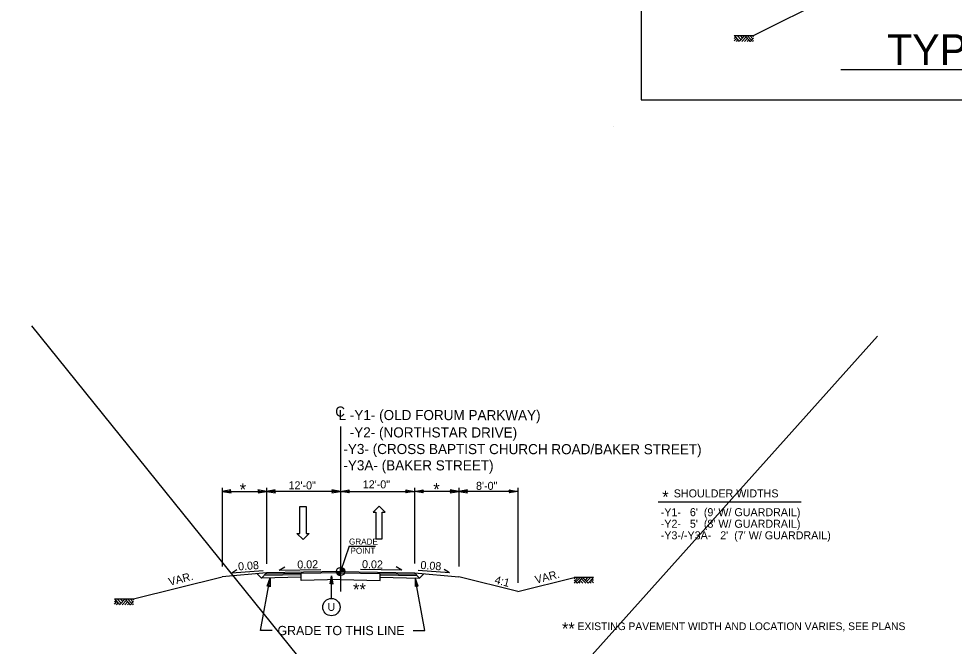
# Model space of a CAD drawing. Extents: x 1904401 to 1905163, y 193929 to 194736.
# Drawn here: x 1904401.4 to 1904553.3, y 194143.4 to 194245.4 of the extents above; entities that cross this region are included whole.
import ezdxf

# ---------------------------------------------------------------- set-up
doc = ezdxf.new("R2010")
doc.units = 0
for name, color, linetype in [('Old_Level_1', 7, 'Continuous'), ('Old_Level_11', 7, 'Continuous'), ('Old_Level_2', 7, 'Continuous'), ('Old_Level_20', 7, 'Continuous'), ('Old_Level_3', 7, 'Continuous'), ('Prop Dimension Text', 7, 'Continuous'), ('Prop Lane Arrow CELL', 7, 'Continuous'), ('Scratch_Level_3', 7, 'Continuous'), ('Typical Arrow Superelevation CELL', 7, 'Continuous'), ('Typical Berm CELL', 7, 'Continuous'), ('Typical Hinge Slope Arterial CELL', 7, 'Continuous'), ('Typical Hinge Slope Interstate CELL', 7, 'Continuous'), ('Typical Terminator CELL', 7, 'Continuous'), ('Typical Text Centerline CELL', 7, 'Continuous')]:
    doc.layers.add(name, color=color, linetype=linetype)

msp = doc.modelspace()

# ---------------------------------------------------------------- linework, layer by layer
at = {"layer": 'Old_Level_1'}
for p, q in [((1904453.68, 194155.54), (1904453.68, 194156.22)), ((1904453.01, 194155.54), (1904453.68, 194155.54)), ((1904454.36, 194155.54), (1904453.68, 194155.54)), ((1904453.68, 194154.87), (1904453.68, 194155.54)), ((1904453.68, 194155.54), (1904453.68, 194154.87))]:
    msp.add_line(p, q, dxfattribs=at)
for points in [[(1904453.69, 194156.22), (1904453.69, 194156.22), (1904453.69, 194155.54)], [(1904453.7, 194156.22), (1904453.7, 194155.54)], [(1904453.72, 194156.22), (1904453.72, 194155.54)], [(1904453.73, 194156.22), (1904453.73, 194155.54)], [(1904453.74, 194156.21), (1904453.74, 194155.54)], [(1904453.76, 194156.21), (1904453.76, 194155.54)], [(1904453.77, 194156.21), (1904453.77, 194155.54)], [(1904453.78, 194156.21), (1904453.78, 194155.54)], [(1904453.8, 194156.21), (1904453.8, 194155.54)], [(1904453.81, 194156.21), (1904453.81, 194155.54)], [(1904453.82, 194156.2), (1904453.82, 194155.54)], [(1904453.84, 194156.2), (1904453.84, 194155.54)], [(1904453.85, 194156.2), (1904453.85, 194155.54)], [(1904453.86, 194156.19), (1904453.86, 194155.54)], [(1904453.88, 194156.19), (1904453.88, 194155.54)], [(1904453.89, 194156.18), (1904453.89, 194155.54)], [(1904453.91, 194156.18), (1904453.91, 194155.54)], [(1904453.92, 194156.18), (1904453.92, 194155.54)], [(1904453.93, 194156.17), (1904453.93, 194155.54)], [(1904453.95, 194156.16), (1904453.95, 194155.54)], [(1904453.96, 194156.16), (1904453.96, 194155.54)], [(1904453.97, 194156.15), (1904453.97, 194155.54)], [(1904453.99, 194156.15), (1904453.99, 194155.54)], [(1904454, 194156.14), (1904454, 194155.54)], [(1904454.01, 194156.13), (1904454.01, 194155.54)], [(1904454.03, 194156.12), (1904454.03, 194155.54)], [(1904454.04, 194156.12), (1904454.04, 194155.54)], [(1904454.05, 194156.11), (1904454.05, 194155.54)], [(1904454.07, 194156.1), (1904454.07, 194155.54)], [(1904454.08, 194156.09), (1904454.08, 194155.54)], [(1904454.09, 194156.08), (1904454.09, 194155.54)], [(1904454.11, 194156.07), (1904454.11, 194155.54)], [(1904454.12, 194156.06), (1904454.12, 194155.54)], [(1904454.13, 194156.04), (1904454.13, 194155.54)], [(1904454.15, 194156.03), (1904454.15, 194155.54)], [(1904454.16, 194156.02), (1904454.16, 194155.54)], [(1904454.18, 194156), (1904454.18, 194155.54)], [(1904454.19, 194155.99), (1904454.19, 194155.54)], [(1904454.2, 194155.97), (1904454.2, 194155.54)], [(1904454.22, 194155.96), (1904454.22, 194155.54)], [(1904454.23, 194155.94), (1904454.23, 194155.54)], [(1904453.01, 194155.54), (1904453.01, 194155.47)], [(1904453.02, 194155.54), (1904453.02, 194155.39)], [(1904453.04, 194155.54), (1904453.04, 194155.34)], [(1904453.05, 194155.54), (1904453.05, 194155.3)], [(1904453.07, 194155.54), (1904453.07, 194155.27)], [(1904453.08, 194155.54), (1904453.08, 194155.24)], [(1904453.09, 194155.54), (1904453.09, 194155.22)], [(1904453.11, 194155.54), (1904453.11, 194155.19)], [(1904453.12, 194155.54), (1904453.12, 194155.17)], [(1904453.13, 194155.54), (1904453.13, 194155.15)], [(1904453.15, 194155.54), (1904453.15, 194155.13)], [(1904453.16, 194155.54), (1904453.16, 194155.12)], [(1904453.17, 194155.54), (1904453.17, 194155.1)], [(1904453.19, 194155.54), (1904453.19, 194155.09)], [(1904453.2, 194155.54), (1904453.2, 194155.07)], [(1904453.21, 194155.54), (1904453.21, 194155.06)], [(1904453.23, 194155.54), (1904453.23, 194155.04)], [(1904453.24, 194155.54), (1904453.24, 194155.03)], [(1904453.25, 194155.54), (1904453.25, 194155.02)], [(1904453.27, 194155.54), (1904453.27, 194155.01)], [(1904453.28, 194155.54), (1904453.28, 194155)], [(1904453.29, 194155.54), (1904453.29, 194154.99)], [(1904453.31, 194155.54), (1904453.31, 194154.98)], [(1904453.32, 194155.54), (1904453.32, 194154.97)], [(1904453.34, 194155.54), (1904453.34, 194154.96)], [(1904453.35, 194155.54), (1904453.35, 194154.96)], [(1904453.36, 194155.54), (1904453.36, 194154.95)], [(1904453.38, 194155.54), (1904453.38, 194154.94)], [(1904453.39, 194155.54), (1904453.39, 194154.94)], [(1904453.4, 194155.54), (1904453.4, 194154.93)], [(1904453.42, 194155.54), (1904453.42, 194154.92)], [(1904453.43, 194155.54), (1904453.43, 194154.92)], [(1904453.44, 194155.54), (1904453.44, 194154.91)], [(1904453.46, 194155.54), (1904453.46, 194154.91)], [(1904453.47, 194155.54), (1904453.47, 194154.9)], [(1904453.48, 194155.54), (1904453.48, 194154.9)], [(1904453.5, 194155.54), (1904453.5, 194154.89)], [(1904453.51, 194155.54), (1904453.51, 194154.89)], [(1904453.52, 194155.54), (1904453.52, 194154.89)], [(1904453.54, 194155.54), (1904453.54, 194154.88)], [(1904453.55, 194155.54), (1904453.55, 194154.88)], [(1904453.56, 194155.54), (1904453.56, 194154.88)], [(1904453.58, 194155.54), (1904453.58, 194154.88)], [(1904453.59, 194155.54), (1904453.59, 194154.87)], [(1904453.61, 194155.54), (1904453.61, 194154.87)], [(1904453.62, 194155.54), (1904453.62, 194154.87)], [(1904453.63, 194155.54), (1904453.63, 194154.87)], [(1904453.65, 194155.54), (1904453.65, 194154.87)], [(1904453.66, 194155.54), (1904453.66, 194154.87)], [(1904453.67, 194155.54), (1904453.67, 194154.87), (1904453.67, 194154.87)], [(1904454.24, 194155.92), (1904454.24, 194155.54)], [(1904454.26, 194155.9), (1904454.26, 194155.54)], [(1904454.27, 194155.88), (1904454.27, 194155.54)], [(1904454.28, 194155.85), (1904454.28, 194155.54)], [(1904454.3, 194155.82), (1904454.3, 194155.54)], [(1904454.31, 194155.79), (1904454.31, 194155.54)], [(1904454.32, 194155.75), (1904454.32, 194155.54)], [(1904454.34, 194155.71), (1904454.34, 194155.54)], [(1904454.35, 194155.64), (1904454.35, 194155.54)]]:
    msp.add_lwpolyline(points, dxfattribs=at)
msp.add_circle((1904453.68, 194155.54), 0.675, dxfattribs=at)
for start, end in [(359.9905, 89.9905), (179.9905, 269.9905)]:
    msp.add_arc((1904453.68, 194155.54), 0.675, start, end, dxfattribs=at)
at = {"layer": 'Old_Level_11'}
msp.add_line((1904452.2, 194151.16), (1904452.2, 194154.82), dxfattribs=at)
msp.add_lwpolyline([(1904451.97, 194153.51), (1904452.2, 194154.82), (1904452.43, 194153.5), (1904452.2, 194153.67)], close=True, dxfattribs=at)
msp.add_circle((1904452.2, 194149.75), 1.41, dxfattribs=at)
at = {"layer": 'Old_Level_2'}
msp.add_lwpolyline([(1904502.51, 194232.16), (1904658.33, 194232.16), (1904658.33, 194351.23), (1904502.51, 194351.23)], close=True, dxfattribs=at)
at = {"layer": 'Old_Level_3'}
for q in [(1904453.68, 194155.54), (1904459.33, 194159.68)]:
    msp.add_line((1904455.07, 194159.68), q, dxfattribs=at)
at = {"layer": 'Prop Lane Arrow CELL'}
for p, q in [((1904517.6, 194242.62), (1904518.47, 194241.69)), ((1904518.07, 194242.63), (1904518.71, 194241.95)), ((1904518.47, 194241.69), (1904519.35, 194242.63)), ((1904518.55, 194242.63), (1904518.95, 194242.2)), ((1904519.03, 194242.63), (1904519.19, 194242.46)), ((1904519.35, 194242.63), (1904520.24, 194241.68)), ((1904519.73, 194242.63), (1904520.43, 194241.89)), ((1904520.13, 194242.63), (1904520.63, 194242.1)), ((1904520.52, 194242.63), (1904520.72, 194242.41)), ((1904517.6, 194242.14), (1904517.83, 194242.38)), ((1904517.6, 194241.74), (1904518.01, 194242.18)), ((1904517.95, 194241.67), (1904518.22, 194241.96)), ((1904518.32, 194241.67), (1904518.41, 194241.76)), ((1904518.84, 194241.67), (1904519.55, 194242.42)), ((1904519.29, 194241.67), (1904519.77, 194242.18)), ((1904519.73, 194241.67), (1904519.99, 194241.95)), ((1904520.08, 194241.67), (1904520.16, 194241.76)), ((1904520.24, 194241.68), (1904520.72, 194242.2)), ((1904520.56, 194241.67), (1904520.72, 194241.84)), ((1904534.93, 194237.11), (1904616.21, 194237.11)), ((1904403.48, 194195.47), (1904532.3, 194035.74)), ((1904540.87, 194193.76), (1904401.43, 194038.14)), ((1904434.48, 194169.15), (1904434.48, 194156.38)), ((1904434.48, 194168.55), (1904441.68, 194168.55)), ((1904441.68, 194169.15), (1904441.68, 194156.81)), ((1904453.68, 194168.55), (1904441.68, 194168.55)), ((1904453.68, 194168.55), (1904465.68, 194168.55)), ((1904465.68, 194169.15), (1904465.68, 194156.84)), ((1904482.48, 194168.55), (1904465.68, 194168.55)), ((1904472.88, 194169.15), (1904472.88, 194156.38)), ((1904482.48, 194169.15), (1904482.48, 194153.71)), ((1904505.24, 194166.86), (1904528.48, 194166.86)), ((1904447.08, 194166.08), (1904448.1, 194166.08)), ((1904447.08, 194161.73), (1904447.08, 194166.08)), ((1904448.1, 194166.08), (1904448.1, 194161.73)), ((1904459.96, 194166.18), (1904458.97, 194165.2)), ((1904458.97, 194165.2), (1904459.43, 194165.2)), ((1904459.43, 194165.2), (1904459.43, 194160.84)), ((1904460.93, 194165.2), (1904459.96, 194166.18)), ((1904460.46, 194160.84), (1904460.46, 194165.2)), ((1904460.46, 194165.2), (1904460.93, 194165.2)), ((1904447.61, 194160.74), (1904446.61, 194161.73)), ((1904446.61, 194161.73), (1904447.08, 194161.73)), ((1904448.57, 194161.73), (1904447.61, 194160.74)), ((1904448.1, 194161.73), (1904448.57, 194161.73)), ((1904459.43, 194160.84), (1904460.46, 194160.84)), ((1904441.68, 194155.3), (1904434.48, 194154.7)), ((1904440.86, 194154.48), (1904440.17, 194155.18)), ((1904440.7, 194145.97), (1904442.28, 194154.51)), ((1904440.86, 194154.48), (1904441.68, 194155.3)), ((1904447.28, 194154.61), (1904440.86, 194154.48)), ((1904447.28, 194155.01), (1904441.27, 194154.89)), ((1904447.28, 194155.22), (1904441.48, 194155.1)), ((1904453.68, 194155.54), (1904441.68, 194155.3)), ((1904453.68, 194155.54), (1904465.68, 194155.3)), ((1904460.1, 194155.22), (1904465.88, 194155.1)), ((1904460.1, 194155.01), (1904466.09, 194154.89)), ((1904460.1, 194154.61), (1904466.5, 194154.48)), ((1904466.5, 194154.48), (1904465.68, 194155.3)), ((1904465.68, 194155.3), (1904472.88, 194154.7)), ((1904467.37, 194145.97), (1904465.79, 194154.51)), ((1904466.5, 194154.48), (1904467.2, 194155.18)), ((1904491.81, 194154.58), (1904491.61, 194154.36)), ((1904492.2, 194154.58), (1904491.7, 194154.05)), ((1904492.6, 194154.58), (1904491.9, 194153.84)), ((1904492.98, 194154.58), (1904492.09, 194153.63)), ((1904493.86, 194153.64), (1904492.98, 194154.58)), ((1904493.3, 194154.58), (1904493.14, 194154.41)), ((1904493.78, 194154.58), (1904493.38, 194154.15)), ((1904494.26, 194154.58), (1904493.62, 194153.9)), ((1904494.73, 194154.57), (1904493.86, 194153.64)), ((1904492.09, 194153.63), (1904491.61, 194154.15)), ((1904491.77, 194153.62), (1904491.61, 194153.79)), ((1904492.25, 194153.62), (1904492.17, 194153.71)), ((1904492.61, 194153.62), (1904492.35, 194153.9)), ((1904493.04, 194153.62), (1904492.56, 194154.13)), ((1904493.49, 194153.62), (1904492.79, 194154.37)), ((1904494.01, 194153.62), (1904493.93, 194153.71)), ((1904494.38, 194153.62), (1904494.11, 194153.91)), ((1904494.73, 194153.69), (1904494.32, 194154.13)), ((1904494.73, 194154.09), (1904494.51, 194154.33)), ((1904416.96, 194151.09), (1904417.83, 194150.16)), ((1904416.96, 194150.61), (1904417.19, 194150.85)), ((1904416.96, 194150.21), (1904417.37, 194150.65)), ((1904417.31, 194150.14), (1904417.58, 194150.43)), ((1904417.43, 194151.1), (1904418.07, 194150.42)), ((1904417.68, 194150.14), (1904417.77, 194150.23)), ((1904417.83, 194150.16), (1904418.71, 194151.1)), ((1904417.91, 194151.1), (1904418.31, 194150.67)), ((1904418.2, 194150.14), (1904418.91, 194150.89)), ((1904418.39, 194151.1), (1904418.55, 194150.93)), ((1904418.65, 194150.14), (1904419.13, 194150.65)), ((1904418.71, 194151.1), (1904419.6, 194150.15)), ((1904419.09, 194150.14), (1904419.35, 194150.42)), ((1904419.1, 194151.1), (1904419.79, 194150.36)), ((1904419.44, 194150.14), (1904419.52, 194150.23)), ((1904419.5, 194151.1), (1904419.99, 194150.57)), ((1904419.6, 194150.15), (1904420.08, 194150.67)), ((1904419.88, 194151.1), (1904420.08, 194150.88)), ((1904419.92, 194150.14), (1904420.08, 194150.31)), ((1904442.6, 194145.97), (1904440.7, 194145.97)), ((1904465.47, 194145.97), (1904467.37, 194145.97))]:
    msp.add_line(p, q, dxfattribs=at)
for points in [[(1904517.6, 194242.63), (1904520.72, 194242.63)], [(1904494.73, 194154.58), (1904491.61, 194154.58)], [(1904416.96, 194151.1), (1904420.08, 194151.1)]]:
    msp.add_lwpolyline(points, dxfattribs=at)
at = {"layer": 'Scratch_Level_3'}
msp.add_line((1904497.98, 194227.92), (1904497.98, 194227.92), dxfattribs=at)
at = {"layer": 'Typical Arrow Superelevation CELL'}
for p, q in [((1904443.72, 194155.75), (1904444.66, 194156.32)), ((1904463.65, 194155.75), (1904462.71, 194156.32)), ((1904436.02, 194155.31), (1904436.85, 194155.88)), ((1904436.02, 194155.31), (1904441.1, 194155.69)), ((1904443.72, 194155.75), (1904450.47, 194155.89)), ((1904463.65, 194155.75), (1904456.9, 194155.89)), ((1904471.35, 194155.31), (1904466.27, 194155.69)), ((1904471.35, 194155.31), (1904470.52, 194155.88))]:
    msp.add_line(p, q, dxfattribs=at)
at = {"layer": 'Typical Berm CELL'}
for p, q in [((1904453.7, 194155.35), (1904447.28, 194155.22)), ((1904447.28, 194154.1), (1904447.28, 194155.22)), ((1904453.68, 194155.35), (1904460.1, 194155.22)), ((1904460.1, 194154.1), (1904460.1, 194155.22)), ((1904453.7, 194154.23), (1904447.28, 194154.1)), ((1904453.68, 194154.23), (1904460.1, 194154.1))]:
    msp.add_line(p, q, dxfattribs=at)
at = {"layer": 'Typical Hinge Slope Arterial CELL'}
msp.add_line((1904520.72, 194242.63), (1904550.72, 194257.63), dxfattribs=at)
at = {"layer": 'Typical Hinge Slope Interstate CELL'}
for p, q in [((1904420.08, 194151.1), (1904434.48, 194154.7)), ((1904482.48, 194152.3), (1904472.88, 194154.7)), ((1904482.48, 194152.3), (1904491.61, 194154.58))]:
    msp.add_line(p, q, dxfattribs=at)
at = {"layer": 'Typical Terminator CELL'}
for points in [[(1904435.89, 194168.79), (1904434.48, 194168.55), (1904435.9, 194168.3), (1904435.72, 194168.55)], [(1904440.28, 194168.31), (1904441.68, 194168.55), (1904440.27, 194168.8), (1904440.45, 194168.55)], [(1904443.09, 194168.79), (1904441.68, 194168.55), (1904443.1, 194168.3), (1904442.92, 194168.55)], [(1904452.28, 194168.31), (1904453.68, 194168.55), (1904452.27, 194168.8), (1904452.45, 194168.55)], [(1904455.09, 194168.31), (1904453.68, 194168.55), (1904455.1, 194168.8), (1904454.92, 194168.55)], [(1904464.28, 194168.79), (1904465.68, 194168.55), (1904464.27, 194168.3), (1904464.45, 194168.55)], [(1904467.09, 194168.31), (1904465.68, 194168.55), (1904467.1, 194168.8), (1904466.92, 194168.55)], [(1904471.48, 194168.31), (1904472.88, 194168.55), (1904471.47, 194168.8), (1904471.65, 194168.55)], [(1904474.29, 194168.79), (1904472.88, 194168.55), (1904474.3, 194168.3), (1904474.12, 194168.55)], [(1904481.08, 194168.79), (1904482.48, 194168.55), (1904481.07, 194168.3), (1904481.25, 194168.55)], [(1904441.79, 194153.17), (1904442.28, 194154.51), (1904442.27, 194153.07), (1904442.06, 194153.3)], [(1904466.28, 194153.17), (1904465.79, 194154.51), (1904465.8, 194153.08), (1904466.01, 194153.3)]]:
    msp.add_lwpolyline(points, close=True, dxfattribs=at)
at = {"layer": 'Typical Text Centerline CELL'}
msp.add_line((1904453.68, 194179.1), (1904453.68, 194152.31), dxfattribs=at)

# ---------------------------------------------------------------- texts
at = {"layer": 'Old_Level_11'}
for s, p in [('GRADE', (1904455.06, 194159.91)), ('POINT', (1904455.3, 194158.42))]:
    msp.add_text(s, height=0.984, dxfattribs=at).set_placement(p)
at = {"layer": 'Old_Level_20'}
msp.add_text('U', height=1.28, dxfattribs=at).set_placement((1904451.57, 194149.15))
at = {"layer": 'Prop Dimension Text'}
for rotation, p in [(1.1462, (1904446.67, 194156.02)), (358.8538, (1904457.16, 194156.09))]:
    msp.add_text('0.02', height=1.3, rotation=rotation, dxfattribs=at).set_placement(p)
at = {"layer": 'Prop Lane Arrow CELL'}
for s, height, p in [('TYPICAL SECTION 3', 5, (1904542.41, 194237.83)), ('*', 2, (1904437.3, 194167.87)), ('12\'-0"', 1.3, (1904445.24, 194168.89)), ('12\'-0"', 1.3, (1904457.29, 194169.05)), ('*', 2, (1904468.74, 194167.91)), ('8\'-0"', 1.3, (1904475.68, 194168.81)), ('*', 2, (1904505.91, 194166.66)), ('SHOULDER WIDTHS', 1.3, (1904507.79, 194167.58)), ("-Y1-   6'  (9' W/ GUARDRAIL)", 1.3, (1904505.67, 194164.53)), ("-Y2-   5'  (8' W/ GUARDRAIL)", 1.3, (1904505.67, 194162.65)), ("-Y3-/-Y3A-   2'  (7' W/ GUARDRAIL)", 1.3, (1904505.67, 194160.77)), ('**', 2, (1904455.71, 194151.63)), ('**', 2, (1904489.63, 194145.26)), ('EXISTING PAVEMENT WIDTH AND LOCATION VARIES, SEE PLANS', 1.25, (1904492.17, 194146.02))]:
    msp.add_text(s, height=height, dxfattribs=at).set_placement(p)
for s, height, rotation, p in [('0.08', 1.3, 4.1982, (1904437.09, 194155.71)), ('0.08', 1.3, 355.8018, (1904466.62, 194155.97)), ('GRADE TO THIS LINE', 1.5, 0.0002, (1904443.45, 194145.2))]:
    msp.add_text(s, height=height, rotation=rotation, dxfattribs=at).set_placement(p)
at = {"layer": 'Typical Hinge Slope Interstate CELL'}
for s, rotation, p in [('VAR.', 14.4716, (1904425.94, 194153.2)), ('4:1', 345.5284, (1904478.61, 194153.62)), ('VAR.', 14.4716, (1904485.43, 194153.54))]:
    msp.add_text(s, height=1.3, rotation=rotation, dxfattribs=at).set_placement(p)
at = {"layer": 'Typical Text Centerline CELL'}
msp.add_text('C', height=1.64, dxfattribs=at).set_placement((1904452.82, 194180.71))
for s, p in [('L -Y1- (OLD FORUM PARKWAY) ', (1904453.36, 194180.15)), ('-Y2- (NORTHSTAR DRIVE) ', (1904455.17, 194177.33)), (' -Y3- (CROSS BAPTIST CHURCH ROAD/BAKER STREET) ', (1904453.53, 194174.63)), (' -Y3A- (BAKER STREET) ', (1904453.53, 194171.98))]:
    msp.add_text(s, height=1.6411, rotation=359.9469, dxfattribs=at).set_placement(p)

doc.saveas('drawing.dxf')
